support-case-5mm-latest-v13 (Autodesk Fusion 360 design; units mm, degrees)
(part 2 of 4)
sketch "Sketch28" plane through (0, 0, 19.25) normal (0, 0, 1) x axis (-1, 0, 0)
  line L1 (-86.4, -52.5) -> (-80.4, -52.5)
  line L2 (-86.4, -3.4983) -> (-86.4, -52.5)
  line L3 (-80.4, -3.4983) -> (-86.4, -3.4983)
  line L4 (-80.4, -52.5) -> (-80.4, -3.4983)
  line L5 (-22.4, -3.5) -> (-28.4, -3.5)
  line L6 (-22.4, -52.5) -> (-22.4, -3.5)
  line L7 (-28.4, -52.5) -> (-22.4, -52.5)
  line L8 (-28.4, -3.5) -> (-28.4, -52.5)
  line L9 (-25.4, -49.5) -> (-83.4, -49.5)
  line L10 (-25.4, -55.5) -> (-25.4, -49.5)
  line L11 (-83.4, -55.5) -> (-25.4, -55.5)
  line L12 (-83.4, -49.5) -> (-83.4, -55.5)
  line L13 (-74.4, -49.5) -> (-80.4, -49.5)
  line L14 (-80.4, -43.5) -> (-80.4, -49.5)
  line L15 (-74.4, -49.5) -> (-80.4, -43.5)
  line L16 (-34.4, -49.5) -> (-28.4, -49.5)
  line L17 (-28.4, -43.5) -> (-28.4, -49.5)
  line L18 (-28.4, -43.5) -> (-34.4, -49.5)
  circle C1 centre (-83.4, -3.5) radius 3
  circle C2 centre (-83.4, -52.5) radius 3
  circle C3 centre (-25.4, -52.5) radius 3
  point P5 (-86.4, -3.4983)
  point P13 (-25.4, -55.5)
  point P11 (-83.4, -49.5)
  point P17 (-80.4, -49.5)
  point P20 (-28.4, -49.5)
  point P18 (-74.4, -49.5)
  point P19 (-80.4, -43.5)
  point P21 (-34.4, -49.5)
  point P22 (-28.4, -43.5)
  horizontal L1
  vertical L2
  horizontal L3
  vertical L4
  coincident C1 P5
  horizontal L5
  vertical L6
  horizontal L7
  vertical L8
  horizontal L9
  vertical L10
  horizontal L11
  vertical L12
  coincident P13 C3
  coincident P11 C2
  coincident L9 P17
  coincident L4 P17
  perpendicular L4 L13
  perpendicular L9 L14
  coincident L8 P20
  coincident L9 P20
  perpendicular L8 L16
  perpendicular L9 L17
  dimension "d218" distance P17 P18 = 6
  dimension "d219" distance P17 P19 = 6
  dimension "d220" distance P20 P21 = 6
  dimension "d221" distance P20 P22 = 6
extrude "Extrude30" add sketch "Sketch28" along normal blind 1
extrude "Extrude31" add of existing geometry blind 2
fillet "Fillet25" radius 10.5
move "Move3"
extrude "Extrude32" add of existing geometry blind 1.85
offset_faces "OffsetFaces6" distance -0.2
offset_faces "OffsetFaces7" distance -0.2
combine "Combine2"
work_plane "WorkPlane3" AlongDistance 1
sketch "Sketch29" plane through (88.7, 27.8941, 21.675) normal (1, 0, 0) x axis (0, 1, 0)
  line L1 (25, 0) -> (-25, 0)
  line L2 (13, -1.5) -> (13, 0)
  line L3 (-13, 0) -> (0, 0)
  line L4 (-13, -2) -> (-13, 0)
  line L5 (13, 0) -> (-13, 0)
  line L6 (13, -1.5) -> (13, 0)
  line L7 (-13, -1.5) -> (13, -1.5)
  line L8 (-13, 0) -> (-13, -1.5)
  point P1 (0, 0)
  point P6 (0, 0)
  point P4 (13, 0)
  point P7 (-13, 0)
  horizontal L1
  vertical L2
  horizontal L3
  vertical L4
  coincident P1 P6
  horizontal L5
  vertical L6
  horizontal L7
  vertical L8
  dimension "d233" distance P1 P4 = 13
  dimension "d235" distance P6 P7 = 13
  dimension "d237" distance L3 L7 = 1.5
revolve "Revolve3" sketch "Sketch29" AlongAngle 360
fillet "Fillet26" radius 1
sketch "Sketch30" plane through (0, 0, 23.1) normal (0, 0, 1) x axis (-1, 0, 0)
  line L1 (-4.6, -56.802) -> (-84.2, -56.802)
  line L2 (-1.1, -2.6862) -> (-1.1, -53.302)
  line L3 (-84.4, 0.8138) -> (-4.6, 0.8138)
  line L4 (-87.7, -53.302) -> (-87.7, -2.4862)
  line L5 (-86.7, -53.302) -> (-86.7, -2.4862)
  line L6 (-4.6, -55.802) -> (-84.2, -55.802)
  line L7 (-2.1, -2.6862) -> (-2.1, -53.302)
  line L8 (-84.4, -0.1862) -> (-4.6, -0.1862)
  arc A1 centre (-84.2, -53.302) radius 3.5 clockwise from (-84.2, -56.802) to (-87.7, -53.302)
  arc A2 centre (-4.6, -53.302) radius 3.5 clockwise from (-1.1, -53.302) to (-4.6, -56.802)
  arc A3 centre (-4.6, -2.6862) radius 3.5 clockwise from (-4.6, 0.8138) to (-1.1, -2.6862)
  arc A4 centre (-84.4, -2.4862) radius 3.3 clockwise from (-87.7, -2.4862) to (-84.4, 0.8138)
  arc A5 centre (-84.2, -53.302) radius 2.5 clockwise from (-84.2, -55.802) to (-86.7, -53.302)
  arc A6 centre (-4.6, -53.302) radius 2.5 clockwise from (-2.1, -53.302) to (-4.6, -55.802)
  arc A7 centre (-4.6, -2.6862) radius 2.5 clockwise from (-4.6, -0.1862) to (-2.1, -2.6862)
  arc A8 centre (-84.4, -2.4862) radius 2.3 clockwise from (-86.7, -2.4862) to (-84.4, -0.1862)
  circle C1 centre (-44.4, -27.9441) radius 5
  circle C2 centre (-44.4, -27.9441) radius 7
  circle C3 centre (-44.4, -27.9441) radius 10
  circle C4 centre (-44.4, -27.9441) radius 12
  circle C5 centre (-44.4, -27.9441) radius 15
  circle C6 centre (-44.4, -27.9441) radius 17
  circle C7 centre (-44.4, -27.9441) radius 20
  circle C8 centre (-44.4, -27.9441) radius 22
  circle C9 centre (-44.4, -27.9441) radius 25
  circle C10 centre (-44.4, -27.9441) radius 27
  circle C11 centre (-44.4, -27.9441) radius 30
  circle C12 centre (-44.4, -27.9441) radius 32
  circle C13 centre (-44.4, -27.9441) radius 35
  circle C14 centre (-44.4, -27.9441) radius 37.5
  circle C15 centre (-44.4, -27.9441) radius 40
  circle C16 centre (-44.4, -27.9441) radius 42
  circle C17 centre (-44.4, -27.9441) radius 45
  circle C18 centre (-44.4, -27.9441) radius 47
  concentric C1 C3
  concentric C1 C4
  concentric C4 C5
  concentric C1 C6
  concentric C4 C7
  concentric C5 C8
  concentric C7 C9
  concentric C4 C10
  concentric C4 C11
  concentric C8 C12
  concentric C7 C13
  concentric C7 C14
  concentric C11 C15
  concentric C14 C16
  concentric C9 C17
  concentric C16 C18
  dimension "d241" = -1
  dimension "d242" diameter C1 = 10
  dimension "d243" = 2
  dimension "d244" diameter C3 = 20
  dimension "d245" diameter C4 = 24
  dimension "d246" diameter C5 = 30
  dimension "d247" diameter C6 = 34
  dimension "d248" diameter C7 = 40
  dimension "d249" diameter C8 = 44
  dimension "d250" diameter C9 = 50
  dimension "d251" diameter C10 = 54
  dimension "d252" diameter C11 = 60
  dimension "d253" diameter C12 = 64
  dimension "d254" diameter C13 = 70
  dimension "d255" diameter C14 = 75
  dimension "d256" diameter C15 = 80
  dimension "d257" diameter C16 = 84
  dimension "d258" diameter C17 = 90
  dimension "d259" diameter C18 = 94
extrude "Extrude33" cut sketch "Sketch30" profile of A8 L5 A5 L6 A6 L8 L7 A7 C1 C2 C3 C4 C5 C6 C7 C8 C9 C10 C11 C12 C13 C14 C15 C16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 against normal blind 2.85
sketch "Sketch31" plane through (0, 0, 23.1) normal (0, 0, 1) x axis (-1, 0, 0)
  line L1 (-28.6539, -55.802) -> (-23.2118, -55.802)
  line L2 (-23.081, -0.1862) -> (-28.4783, -0.1862)
  line L3 (-75.9198, -0.1862) -> (-79.8189, -0.1862)
  line L4 (-79.7403, -55.802) -> (-75.8315, -55.802)
  line L5 (-86.7, -12.5913) -> (-86.7, -43.297)
  line L6 (-69.6141, -0.1862) -> (-73.2011, -0.1862)
  line L7 (-73.1043, -55.802) -> (-69.5036, -55.802)
  line L8 (-12.9685, -55.802) -> (-9.0597, -55.802)
  line L9 (-8.9811, -0.1862) -> (-12.8802, -0.1862)
  line L10 (-2.1, -43.297) -> (-2.1, -12.5913)
  line L11 (-6.5458, -55.802) -> (-4.6, -55.802)
  line L12 (-2.1, -53.302) -> (-2.1, -48.4309)
  line L13 (-19.2964, -55.802) -> (-15.6957, -55.802)
  line L14 (-15.5989, -0.1862) -> (-19.1859, -0.1862)
  line L15 (-33.0202, -0.1862) -> (-55.7798, -0.1862)
  line L16 (-55.5328, -55.802) -> (-33.2672, -55.802)
  line L17 (-82.3276, -0.1862) -> (-84.4, -0.1862)
  line L18 (-86.7, -2.4862) -> (-86.7, -7.4573)
  line L19 (-60.3217, -0.1862) -> (-65.719, -0.1862)
  line L20 (-65.5882, -55.802) -> (-60.1461, -55.802)
  line L21 (-2.1, -7.4573) -> (-2.1, -2.6862)
  line L22 (-4.6, -0.1862) -> (-6.4724, -0.1862)
  line L23 (-86.7, -48.4309) -> (-86.7, -53.302)
  line L24 (-84.2, -55.802) -> (-82.2542, -55.802)
  line L25 (-4.6, -56.802) -> (-84.2, -56.802)
  line L26 (-1.1, -2.6862) -> (-1.1, -53.302)
  line L27 (-84.4, 0.8138) -> (-4.6, 0.8138)
  line L28 (-87.7, -53.302) -> (-87.7, -2.4862)
  line L29 (-86.7, -2.4862) -> (-84.4, -0.1862)
  line L30 (-86.0263, -0.8599) -> (-85.55, -1.3362)
  curve K1 (-44.4, -27.9441) -> (-2.8322, -0.9185)
  curve K2 (-2.2872, -1.7569) -> (-86.5717, -1.6981)
  curve K3 (-3.3773, -0.0801) -> (-85.481, -0.0217)
  line L31 (9.9934, -28.0452) -> (-44.4, -27.9441)
  curve K4 (-3.4811, -55.9604) -> (-85.5844, -55.7137)
  curve K5 (-2.3847, -54.2877) -> (-86.6689, -54.0333)
  line L32 (-86.8, -54.8) -> (-86.6689, -54.0333)
  line L33 (-85.5844, -55.7137) -> (-86.8, -54.8)
  line L34 (-2.2132, -54.4166) -> (-2.3847, -54.2877)
  line L35 (-3.4811, -55.9604) -> (-2.2132, -54.4166)
  line L36 (-2.087, -1.05) -> (-3.3773, -0.0801)
  line L37 (-2.2872, -1.7569) -> (-2.087, -1.05)
  line L38 (-86.5717, -0.8599) -> (-86.5717, -1.6981)
  line L39 (-85.481, -0.0217) -> (-86.5717, -0.8599)
  arc A1 centre (-44.4, -27.9441) radius 35 clockwise from (-23.081, -0.1862) to (-23.2118, -55.802)
  arc A2 centre (-44.4, -27.9441) radius 32 clockwise from (-28.4783, -0.1862) to (-28.6539, -55.802)
  arc A3 centre (-44.4, -27.9441) radius 45 clockwise from (-86.7, -12.5913) to (-79.8189, -0.1862)
  arc A4 centre (-44.4, -27.9441) radius 42 clockwise from (-75.8315, -55.802) to (-75.9198, -0.1862)
  arc A5 centre (-44.4, -27.9441) radius 45 clockwise from (-79.7403, -55.802) to (-86.7, -43.297)
  arc A6 centre (-44.4, -27.9441) radius 40 clockwise from (-73.1043, -55.802) to (-73.2011, -0.1862)
  arc A7 centre (-44.4, -27.9441) radius 37.5 clockwise from (-69.5036, -55.802) to (-69.6141, -0.1862)
  arc A8 centre (-44.4, -27.9441) radius 45 clockwise from (-2.1, -43.297) to (-9.0597, -55.802)
  arc A9 centre (-44.4, -27.9441) radius 42 clockwise from (-12.8802, -0.1862) to (-12.9685, -55.802)
  arc A10 centre (-44.4, -27.9441) radius 45 clockwise from (-8.9811, -0.1862) to (-2.1, -12.5913)
  arc A11 centre (-4.6, -53.302) radius 2.5 clockwise from (-2.1, -53.302) to (-4.6, -55.802)
  arc A12 centre (-44.4, -27.9441) radius 47 clockwise from (-2.1, -48.4309) to (-6.5458, -55.802)
  arc A13 centre (-44.4, -27.9441) radius 40 clockwise from (-15.5989, -0.1862) to (-15.6957, -55.802)
  arc A14 centre (-44.4, -27.9441) radius 37.5 clockwise from (-19.1859, -0.1862) to (-19.2964, -55.802)
  arc A15 centre (-44.4, -27.9441) radius 30 clockwise from (-33.0202, -0.1862) to (-33.2672, -55.802)
  arc A16 centre (-44.4, -27.9441) radius 30 clockwise from (-55.5328, -55.802) to (-55.7798, -0.1862)
  arc A17 centre (-84.4, -2.4862) radius 2.3 clockwise from (-86.7, -2.4862) to (-84.4, -0.1862)
  arc A18 centre (-44.4, -27.9441) radius 47 clockwise from (-86.7, -7.4573) to (-82.3276, -0.1862)
  arc A19 centre (-44.4, -27.9441) radius 35 clockwise from (-65.5882, -55.802) to (-65.719, -0.1862)
  arc A20 centre (-44.4, -27.9441) radius 32 clockwise from (-60.1461, -55.802) to (-60.3217, -0.1862)
  arc A21 centre (-4.6, -2.6862) radius 2.5 clockwise from (-4.6, -0.1862) to (-2.1, -2.6862)
  arc A22 centre (-44.4, -27.9441) radius 47 clockwise from (-6.4724, -0.1862) to (-2.1, -7.4573)
  arc A23 centre (-84.2, -53.302) radius 2.5 clockwise from (-84.2, -55.802) to (-86.7, -53.302)
  arc A24 centre (-44.4, -27.9441) radius 47 clockwise from (-82.2542, -55.802) to (-86.7, -48.4309)
  arc A25 centre (-84.2, -53.302) radius 3.5 clockwise from (-84.2, -56.802) to (-87.7, -53.302)
  arc A26 centre (-4.6, -53.302) radius 3.5 clockwise from (-1.1, -53.302) to (-4.6, -56.802)
  arc A27 centre (-4.6, -2.6862) radius 3.5 clockwise from (-4.6, 0.8138) to (-1.1, -2.6862)
  arc A28 centre (-84.4, -2.4862) radius 3.3 clockwise from (-87.7, -2.4862) to (-84.4, 0.8138)
  point P36 (-84.4, -0.1862)
  point P63 (-84.4, -0.1862)
  point P37 (-86.7, -2.4862)
  point P64 (-86.7, -2.4862)
  point P65 (-85.55, -1.3362)
  point P66 (-86.0263, -0.8599)
  point P67 (-2.8322, -0.9185)
  point P69 (-86.5717, -1.6981)
  point P76 (-86.6689, -54.0333)
  point P70 (-2.2872, -1.7569)
  point P77 (-2.3847, -54.2877)
  point P71 (-85.481, -0.0217)
  point P74 (-85.5844, -55.7137)
  point P72 (-3.3773, -0.0801)
  point P75 (-3.4811, -55.9604)
  coincident P36 P63
  coincident P37 P64
  midpoint L29 P65
  midpoint A17 P66
  midpoint A21 P67
  symmetric P69 L31 P76
  symmetric P70 L31 P77
  symmetric K2 L31 K5
  symmetric P71 L31 P74
  symmetric P72 L31 P75
  symmetric K3 L31 K4
  parallel L33 L34
  parallel L34 L36
  vertical L38
  dimension "d264" = 1
  dimension "d265" = -1
extrude "Extrude34" add sketch "Sketch31" profile of A1 A2 A3 A4 A5 A6 A7 A8 A9 A10 A11 A12 A13 A14 A15 A16 A17 A18 A19 A20 A21 A22 A23 A24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 against normal blind 2.85
extrude "Extrude35" cut of existing geometry blind -0.519
delete_face "DeleteFace9"
delete_face "DeleteFace10"
delete_face "DeleteFace11"
delete_face "DeleteFace12"
extrude "Extrude36" add of existing geometry blind 0.719 (= "2 mm - 1.281 mm")
fillet "Fillet27" radius 1.5
delete_face "DeleteFace13"
move_face "MoveFace1" TranslateX 0.1 TranslateY 0 TranslateZ 0
move_face "MoveFace2" TranslateX 1.3 TranslateY 0 TranslateZ 0
move_face "MoveFace3" TranslateX 0.15 TranslateY 0 TranslateZ 0
move_face "MoveFace4" TranslateX 0.15 TranslateY 0 TranslateZ 0
move_face "MoveFace5" TranslateX 0.05 TranslateY 0 TranslateZ 0
delete_face "DeleteFace14"
delete_face "DeleteFace15"
delete_face "DeleteFace16"
delete_face "DeleteFace17"
delete_face "DeleteFace18"
delete_face "DeleteFace19"
delete_face "DeleteFace20"
delete_face "DeleteFace21"
delete_face "DeleteFace22"
delete_face "DeleteFace23"
delete_face "DeleteFace24"
delete_face "DeleteFace25"
delete_face "DeleteFace26"
delete_face "DeleteFace27"
delete_face "DeleteFace28"
delete_face "DeleteFace29"
delete_face "DeleteFace30"
delete_face "DeleteFace31"
delete_face "DeleteFace32"
delete_face "DeleteFace33"
delete_face "DeleteFace34"
delete_face "DeleteFace35"
delete_face "DeleteFace36"
delete_face "DeleteFace37"
delete_face "DeleteFace38"
delete_face "DeleteFace39"
delete_face "DeleteFace40"
sketch "Sketch32" plane through (0, 58.002, 0) normal (0, 1, 0) x axis (-1, 0, 0)
  line L1 (-71.2, 6.8) -> (-80.2, 6.8)
  line L2 (-70.7, 3) -> (-70.7, 6.3)
  line L3 (-80.2, 2.5) -> (-71.2, 2.5)
  line L4 (-80.7, 6.3) -> (-80.7, 3)
  line L5 (-51.05, 2.5) -> (-43.95, 2.5)
  line L6 (-51.55, 6) -> (-51.55, 3)
  line L7 (-43.95, 6.5) -> (-51.05, 6.5)
  line L8 (-43.45, 3) -> (-43.45, 6)
  line L9 (-64.45, 2.5) -> (-57.35, 2.5)
  line L10 (-64.95, 6) -> (-64.95, 3)
  line L11 (-57.35, 6.5) -> (-64.45, 6.5)
  line L12 (-56.85, 3) -> (-56.85, 6)
  line L13 (-82.05, 1) -> (-82.05, 11.0521)
  line L14 (-28.2507, 1) -> (-82.05, 1)
  line L15 (-28.2507, 11.0521) -> (-28.2507, 1)
  line L16 (-82.05, 11.0521) -> (-28.2507, 11.0521)
  line L17 (-40.45, -0.5) -> (-40.45, 12.5584)
  line L18 (-26.7633, 12.5584) -> (-40.45, 12.5584)
  line L19 (-26.7633, -0.6691) -> (-26.7633, 12.5584)
  line L20 (-40.45, -0.6691) -> (-26.7633, -0.6691)
  line L21 (-40.45, 12.5584) -> (-40.45, -0.6691)
  arc A1 centre (-71.2, 6.3) radius 0.5 clockwise from (-71.2, 6.8) to (-70.7, 6.3)
  arc A2 centre (-71.2, 3) radius 0.5 clockwise from (-70.7, 3) to (-71.2, 2.5)
  arc A3 centre (-80.2, 3) radius 0.5 clockwise from (-80.2, 2.5) to (-80.7, 3)
  arc A4 centre (-80.2, 6.3) radius 0.5 clockwise from (-80.7, 6.3) to (-80.2, 6.8)
  arc A5 centre (-43.95, 3) radius 0.5 clockwise from (-43.45, 3) to (-43.95, 2.5)
  arc A6 centre (-51.05, 3) radius 0.5 clockwise from (-51.05, 2.5) to (-51.55, 3)
  arc A7 centre (-51.05, 6) radius 0.5 clockwise from (-51.55, 6) to (-51.05, 6.5)
  arc A8 centre (-43.95, 6) radius 0.5 clockwise from (-43.95, 6.5) to (-43.45, 6)
  arc A9 centre (-57.35, 3) radius 0.5 clockwise from (-56.85, 3) to (-57.35, 2.5)
  arc A10 centre (-64.45, 3) radius 0.5 clockwise from (-64.45, 2.5) to (-64.95, 3)
  arc A11 centre (-64.45, 6) radius 0.5 clockwise from (-64.95, 6) to (-64.45, 6.5)
  arc A12 centre (-57.35, 6) radius 0.5 clockwise from (-57.35, 6.5) to (-56.85, 6)
  perpendicular L14 L17
  horizontal L18
  vertical L19
  horizontal L20
  vertical L21
  dimension "d289" distance L8 L17 = 3
extrude "Extrude37" add sketch "Sketch32" profile of L14 L15 L16 L17 L18 L19 L20 L21 along normal blind 1.8
delete_face "DeleteFace41"
fillet "Fillet29" radius 1.5
delete_face "DeleteFace43"
sketch "Sketch33" plane through (0, 59.802, 0) normal (0, 1, 0) x axis (-1, 0, 0)
  line L1 (-40.45, -0.4697) -> (-40.45, 12.5218)
  line L2 (-83.5197, -0.4697) -> (-40.45, -0.4697)
  line L3 (-83.5197, 12.5218) -> (-83.5197, -0.4697)
  line L4 (-40.45, 12.5218) -> (-83.5197, 12.5218)
  line L5 (-4.6, -2.019) -> (-84.2, -2.019)
  line L6 (-4.6, 21.6) -> (-4.6, -2.019)
  line L7 (-84.2, 21.6) -> (-4.6, 21.6)
  line L8 (-84.2, -2.019) -> (-84.2, 21.6)
  line L9 (-83.5197, 12.5218) -> (-40.45, 12.5218)
  line L10 (-83.5197, -0.4697) -> (-83.5197, 12.5218)
  line L11 (-40.45, -0.4697) -> (-83.5197, -0.4697)
  line L12 (-40.45, 12.5218) -> (-40.45, -0.4697)
  line L13 (-83.5197, 9.7703) -> (-83.5197, -0.4697)
  line L14 (-40.45, 9.7703) -> (-83.5197, 9.7703)
  point P2 (-40.45, 12.5218)
  point P14 (-40.45, 12.5218)
  point P19 (-40.45, 9.7703)
  point P16 (-83.5197, -0.4697)
  point P18 (-83.5197, 9.7703)
  horizontal L9
  vertical L10
  horizontal L11
  vertical L12
  coincident P2 P14
  perpendicular L11 L13
  coincident L1 P19
  perpendicular L1 L14
  dimension "d330" distance P16 P18 = 10.24 (= "( 5.12 * 2 ) * 1 mm")
extrude "Extrude38" cut sketch "Sketch33" profile of L1 L2 L3 L4 L9 L10 L11 L12 L13 L14 against normal blind 1.8
delete_face "DeleteFace44"
delete_face "DeleteFace46"
delete_face "DeleteFace49"
extrude "Extrude48" add sketch "Sketch33" profile of L1 L3 L4 L9 L10 L12 L14 against normal blind 2.8
extrude "Extrude39" cut of existing geometry blind -0.18 (= "-( 3 mm - 2.82 mm )")
fillet "Fillet30" radius 1.5
delete_face "DeleteFace51"
delete_face "DeleteFace52"
delete_face "DeleteFace53"
delete_face "DeleteFace54"
delete_face "DeleteFace55"
delete_face "DeleteFace56"
delete_face "DeleteFace57"
delete_face "DeleteFace58"
delete_face "DeleteFace59"
delete_face "DeleteFace60"
delete_face "DeleteFace61"
delete_face "DeleteFace62"
delete_face "DeleteFace63"
offset_faces "OffsetFaces8" distance 1
delete_face "DeleteFace64"
extrude "Extrude40" new body of existing geometry blind -2.9
delete_face "DeleteFace65"
combine "Combine3"
combine "Combine4"
extrude "Extrude41" add of existing geometry blind -2.919
extrude "Extrude42" new body of existing geometry blind -2.919
delete_face "DeleteFace66"
extrude "Extrude43" add of existing geometry blind -2.919
fillet "Fillet32" radius 2.25
sketch "Sketch34" plane through (0, 0, -1.519) normal (0, 0, 1) x axis (-1, 0, 0)
  curve K1 (-20.1586, -3.5211) -> (-28.054, 1.0138)
  line L1 (-80.7188, 1.0138) -> (-28.054, 1.0138)
  curve K2 (-80.7188, 1.0138) -> (-78.15, -3.5)
  curve K3 (-78.15, -3.5) -> (-87.9, -6.2042)
  line L2 (-87.9, -19.9875) -> (-87.9, -6.2042)
  line L3 (-84.9, -19.9875) -> (-87.9, -19.9875)
  line L4 (-83.9, -33.6) -> (-83.9, -20.9875)
  line L5 (-87.9, -34.6) -> (-84.9, -34.6)
  line L6 (-87.9, -49.7958) -> (-87.9, -34.6)
  curve K4 (-87.9, -49.7958) -> (-78.15, -52.5)
  curve K5 (-78.15, -52.5) -> (-80.6992, -57.002)
  line L7 (-28.1228, -57.002) -> (-80.6992, -57.002)
  curve K6 (-28.1228, -57.002) -> (-20.1538, -52.5109)
  curve K7 (-20.1538, -52.5109) -> (-22.6848, -57.002)
  line L8 (-4.4, -57.002) -> (-22.6848, -57.002)
  line L9 (-0.9, -2.4862) -> (-0.9, -53.502)
  line L10 (-22.7633, 1.0138) -> (-4.4, 1.0138)
  curve K8 (-22.7633, 1.0138) -> (-20.1586, -3.5211)
  line L11 (-87.7975, -50) -> (-1.0165, -50)
  line L12 (-87.7975, -5) -> (-87.7975, -50)
  line L13 (-1.0165, -5) -> (-87.7975, -5)
  line L14 (-1.0165, -50) -> (-1.0165, -5)
  curve K9
  curve K10
  curve K11
  curve K12
  curve K13
  curve K14
  curve K15
  curve K16
  curve K17
  curve K18
  curve K19
  curve K20
  arc A1 centre (-84.9, -20.9875) radius 1 clockwise from (-84.9, -19.9875) to (-83.9, -20.9875)
  arc A2 centre (-84.9, -33.6) radius 1 clockwise from (-83.9, -33.6) to (-84.9, -34.6)
  arc A3 centre (-4.4, -53.502) radius 3.5 clockwise from (-0.9, -53.502) to (-4.4, -57.002)
  arc A4 centre (-4.4, -2.4862) radius 3.5 clockwise from (-4.4, 1.0138) to (-0.9, -2.4862)
  point P33 (-87.7975, -5)
  point P31 (-1.0165, -50)
  horizontal L11
  vertical L12
  horizontal L13
  vertical L14
  coincident P33
  coincident P31
  coincident P33
  coincident P31
  coincident P33
  dimension "d315" Text1-Height = 4.5
  dimension "d318" Text2-Height = 3.5
  dimension "d471" Text3-Height = 4
extrude "Extrude44" cut sketch "Sketch34" against normal blind 0.2
sketch "Sketch35" plane through (90.7, 0, 0) normal (1, 0, 0) x axis (0, 1, 0)
  line L1 (53.302, -2.019) -> (35.6, -2.019)
  line L2 (53.302, 21.6) -> (53.302, -2.019)
  line L3 (2.6862, 21.6) -> (53.302, 21.6)
  line L4 (2.6862, -2.019) -> (2.6862, 21.6)
  line L5 (18.9875, -2.019) -> (2.6862, -2.019)
  line L6 (18.9875, 0.4) -> (18.9875, -2.019)
  line L7 (33.6, 2.4) -> (20.9875, 2.4)
  line L8 (35.6, -2.019) -> (35.6, 0.4)
  line L9 (53.302, 1.4134) -> (2.6862, 1.4134)
  line L10 (55.9941, 1.4134) -> (27.9941, 1.4134)
  line L11 (37.5941, 1.4134) -> (55.9941, 1.4134)
  line L12 (37.5941, 5.5134) -> (37.5941, 1.4134)
  line L13 (42.6941, 1.4134) -> (55.9941, 1.4134)
  line L14 (42.6941, 5.5134) -> (37.5941, 5.5134)
  line L15 (42.6941, 1.4134) -> (37.5941, 1.4134)
  line L16 (43.8675, 1.7824) -> (43.1406, 5.4642)
  arc A1 centre (20.9875, 0.4) radius 2 clockwise from (18.9875, 0.4) to (20.9875, 2.4)
  arc A2 centre (33.6, 0.4) radius 2 clockwise from (33.6, 2.4) to (35.6, 0.4)
  circle C1 centre (37.5941, 3.4634) radius 2.05
  circle C2 centre (42.6941, 3.4634) radius 2.05
  circle C3 centre (39.6441, 3.4634) radius 2.05
  point P19 (27.9941, 1.4134)
  point P23 (37.5941, 3.4634)
  point P21 (37.5941, 1.4134)
  point P24 (42.6941, 1.4134)
  point P26 (42.6941, 5.5134)
  point P27 (39.6441, 3.4634)
  point P28 (43.1406, 5.4642)
  point P29 (43.8675, 1.7824)
  point P20 (55.9941, 1.4134)
  point P22 (37.5941, 5.5134)
  midpoint L9 P19
  parallel L9 L11
  perpendicular L10 L12
  midpoint L12 P23
  coincident P21 C1
  parallel L11 L13
  coincident P24 C2
  coincident C2 P26
  tangent C2 L14
  perpendicular L12 L14
  tangent C2 L15
  coincident C1 P27
  tangent L15 C3
  coincident C2 P28
  coincident C2 P29
  dimension "d320" distance P19 P20 = 28 (= "( 56 / 2 ) * 1 mm")
  dimension "d321" distance P20 P21 = 18.4
  dimension "d322" distance P21 P22 = 4.1
  dimension "d323" distance P20 P24 = 13.3
extrude "Extrude45" cut sketch "Sketch35" profile of L9 L10 L11 L12 C1 C2 L14 L15 against normal blind 2.8
sketch "Sketch36" plane through (90.7, 0, 0) normal (1, 0, 0) x axis (0, 1, 0)
  line L1 (37.5941, 1.4134) -> (42.6941, 1.4134)
  line L2 (42.6941, 5.5134) -> (37.5941, 5.5134)
  line L3 (33.6, 2.4) -> (20.9875, 2.4)
  line L4 (35.6, -2.019) -> (35.6, 0.4)
  line L5 (53.302, -2.019) -> (35.6, -2.019)
  line L6 (53.302, 21.6) -> (53.302, -2.019)
  line L7 (2.6862, 21.6) -> (53.302, 21.6)
  line L8 (2.6862, -2.019) -> (2.6862, 21.6)
  line L9 (18.9875, -2.019) -> (2.6862, -2.019)
  line L10 (18.9875, 0.4) -> (18.9875, -2.019)
  line L11 (42.0276, 9.5417) -> (40.8255, 7.1376)
  line L12 (38.6336, 8.2336) -> (39.8356, 10.6377)
  line L13 (40.9316, 10.0897) -> (39.7296, 7.6856)
  line L14 (32.6474, 3.0718) -> (31.5271, 3.9384)
  line L15 (32.7999, 5.5837) -> (33.9202, 4.7171)
  line L16 (33.2838, 3.8945) -> (32.1635, 4.7611)
  line L17 (39.809, -1.2436) -> (38.3992, -0.0011)
  line L18 (39.1812, 0.8862) -> (40.591, -0.3564)
  line L19 (40.2, -0.8) -> (38.7902, 0.4426)
  line L20 (36.6258, -0.6871) -> (36.1258, 0.3129)
  line L21 (36.8742, 0.6871) -> (37.3742, -0.3129)
  line L22 (37, -0.5) -> (36.5, 0.5)
  line L23 (44.3847, -0.2206) -> (43.6433, -1.2821)
  line L24 (42.503, -0.4857) -> (43.2444, 0.5758)
  line L25 (44.2127, 0.7478) -> (42.6749, -1.4541)
  line L26 (47.0891, -0.5864) -> (45.9587, 2.459)
  line L27 (47.497, 3.03) -> (48.6275, -0.0154)
  line L28 (48.1438, -1.07) -> (46.4424, 3.5137)
  arc A1 centre (37.5941, 3.4634) radius 2.05 clockwise from (37.5941, 1.4134) to (37.5941, 5.5134)
  arc A2 centre (42.6941, 3.4634) radius 2.05 clockwise from (42.6941, 5.5134) to (42.6941, 1.4134)
  arc A3 centre (33.6, 0.4) radius 2 clockwise from (33.6, 2.4) to (35.6, 0.4)
  arc A4 centre (20.9875, 0.4) radius 2 clockwise from (18.9875, 0.4) to (20.9875, 2.4)
  arc A5 centre (40.9316, 10.0897) radius 1.2254 clockwise from (39.8356, 10.6377) to (42.0276, 9.5417)
  arc A6 centre (39.7296, 7.6856) radius 1.2254 clockwise from (40.8255, 7.1376) to (38.6336, 8.2336)
  arc A7 centre (33.2838, 3.8945) radius 1.0401 clockwise from (33.9202, 4.7171) to (32.6474, 3.0718)
  arc A8 centre (32.1635, 4.7611) radius 1.0401 clockwise from (31.5271, 3.9384) to (32.7999, 5.5837)
  arc A9 centre (40.2, -0.8) radius 0.5914 clockwise from (40.591, -0.3564) to (39.809, -1.2436)
  arc A10 centre (38.7902, 0.4426) radius 0.5914 clockwise from (38.3992, -0.0011) to (39.1812, 0.8862)
  arc A11 centre (37, -0.5) radius 0.4184 clockwise from (37.3742, -0.3129) to (36.6258, -0.6871)
  arc A12 centre (36.5, 0.5) radius 0.4184 clockwise from (36.1258, 0.3129) to (36.8742, 0.6871)
  arc A13 centre (43.8145, 0.1776) radius 0.6955 clockwise from (43.2444, 0.5758) to (44.3847, -0.2206)
  arc A14 centre (43.0731, -0.8839) radius 0.6955 clockwise from (43.6433, -1.2821) to (42.503, -0.4857)
  arc A15 centre (47.8583, -0.3009) radius 0.8205 clockwise from (48.6275, -0.0154) to (47.0891, -0.5864)
  arc A16 centre (46.7279, 2.7445) radius 0.8205 clockwise from (45.9587, 2.459) to (47.497, 3.03)
  point P53 (42.6749, -1.4541)
  point P54 (44.2127, 0.7478)
  point P61 (46.4424, 3.5137)
  point P62 (48.1438, -1.07)
  tangent L11 A5
  tangent A5 L12
  parallel L11 L12
  tangent L12 A6
  tangent L11 A6
  tangent L14 A7
  tangent A7 L15
  parallel L14 L15
  tangent L15 A8
  tangent L14 A8
  tangent L17 A9
  tangent A9 L18
  parallel L17 L18
  tangent L18 A10
  tangent L17 A10
  tangent L20 A11
  tangent A11 L21
  parallel L20 L21
  tangent L21 A12
  tangent L20 A12
  tangent L23 A13
  tangent A13 L24
  parallel L23 L24
  tangent L24 A14
  tangent L23 A14
  midpoint A14 P53
  midpoint A13 P54
  tangent L26 A15
  tangent A15 L27
  parallel L26 L27
  tangent L27 A16
  tangent L26 A16
  midpoint A16 P61
  midpoint A15 P62
extrude "Extrude46" cut sketch "Sketch36" profile of L11 A5 L12 A6 L14 A7 L15 A8 L17 A9 L18 A10 L20 A11 L21 A12 L23 A13 L24 A14 L26 A15 L27 A16 against normal blind 2.8
sketch "Sketch37" plane through (0, 59.802, 0) normal (0, 1, 0) x axis (-1, 0, 0)
  line L1 (-84.2, -2.019) -> (-84.2, 21.6)
  line L2 (-4.6, -2.019) -> (-84.2, -2.019)
  line L3 (-4.6, 21.6) -> (-4.6, -2.019)
  line L4 (-84.2, 21.6) -> (-4.6, 21.6)
  line L5 (-39.5871, -1.2425) -> (-24.6167, -1.2425)
  line L6 (-39.5871, 12.8777) -> (-39.5871, -1.2425)
  line L7 (-34.1048, 11.2793) -> (-36.2337, 8.6349)
  line L8 (-38.0242, 10.0763) -> (-35.8952, 12.7207)
  line L9 (-35, 12) -> (-37.1289, 9.3556)
  line L10 (-35.4481, 3.134) -> (-37.4481, 0.134)
  line L11 (-39.0681, 1.214) -> (-37.0681, 4.214)
  line L12 (-36.2581, 3.674) -> (-38.2581, 0.674)
  line L13 (-29.1506, 11.3422) -> (-32.0744, 7.687)
  line L14 (-34.1698, 9.3632) -> (-31.2459, 13.0183)
  line L15 (-30.1982, 12.1802) -> (-33.1221, 8.5251)
  line L16 (-29.7365, 6.1071) -> (-30.3476, 4.7139)
  line L17 (-31.6524, 5.2861) -> (-31.0413, 6.6794)
  line L18 (-30.3889, 6.3932) -> (-31, 5)
  line L19 (-35.2431, 7.2215) -> (-32.6686, 4.5243)
  line L20 (-33.4899, 3.7403) -> (-36.0645, 6.4375)
  line L21 (-35.6538, 6.8295) -> (-33.0792, 4.1323)
  line L22 (-29.7705, 1.5082) -> (-31.8892, -0.787)
  line L23 (-33.2118, 0.4339) -> (-31.0932, 2.7291)
  line L24 (-30.4319, 2.1186) -> (-32.5505, -0.1766)
  line L25 (-26.7609, 10.6458) -> (-25.751, 8.6279)
  line L26 (-26.9306, 8.0376) -> (-27.9405, 10.0554)
  line L27 (-27.3507, 10.3506) -> (-26.3408, 8.3327)
  line L28 (-27.8127, 5.4623) -> (-29.6231, 7.7754)
  line L29 (-28.5203, 8.6384) -> (-26.71, 6.3254)
  line L30 (-26.8298, 5.3425) -> (-29.5032, 8.7583)
  line L31 (-27.5492, 1.506) -> (-26.5216, 0.4784)
  line L32 (-27.4784, -0.4784) -> (-28.506, 0.5492)
  line L33 (-28.506, 1.506) -> (-26.5216, -0.4784)
  line L34 (-28.5099, 2.5667) -> (-29.1142, 3.171)
  line L35 (-27.8638, 4.4215) -> (-27.2594, 3.8171)
  line L36 (-27.8847, 3.1919) -> (-28.489, 3.7963)
  line L37 (-41.95, 9.7703) -> (-82.1997, 9.7703)
  line L38 (-40.45, 1.0303) -> (-40.45, 8.2703)
  line L39 (-82.1997, -0.4697) -> (-41.95, -0.4697)
  line L40 (-83.6997, 8.2703) -> (-83.6997, 1.0303)
  arc A1 centre (-35, 12) radius 1.1493 clockwise from (-35.8952, 12.7207) to (-34.1048, 11.2793)
  arc A2 centre (-37.1289, 9.3556) radius 1.1493 clockwise from (-36.2337, 8.6349) to (-38.0242, 10.0763)
  arc A3 centre (-36.2581, 3.674) radius 0.9735 clockwise from (-37.0681, 4.214) to (-35.4481, 3.134)
  arc A4 centre (-38.2581, 0.674) radius 0.9735 clockwise from (-37.4481, 0.134) to (-39.0681, 1.214)
  arc A5 centre (-30.1982, 12.1802) radius 1.3416 clockwise from (-31.2459, 13.0183) to (-29.1506, 11.3422)
  arc A6 centre (-33.1221, 8.5251) radius 1.3416 clockwise from (-32.0744, 7.687) to (-34.1698, 9.3632)
  arc A7 centre (-30.3889, 6.3932) radius 0.7124 clockwise from (-31.0413, 6.6794) to (-29.7365, 6.1071)
  arc A8 centre (-31, 5) radius 0.7124 clockwise from (-30.3476, 4.7139) to (-31.6524, 5.2861)
  arc A9 centre (-35.6538, 6.8295) radius 0.5678 clockwise from (-36.0645, 6.4375) to (-35.2431, 7.2215)
  arc A10 centre (-33.0792, 4.1323) radius 0.5678 clockwise from (-32.6686, 4.5243) to (-33.4899, 3.7403)
  arc A11 centre (-30.4319, 2.1186) radius 0.9 clockwise from (-31.0932, 2.7291) to (-29.7705, 1.5082)
  arc A12 centre (-32.5505, -0.1766) radius 0.9 clockwise from (-31.8892, -0.787) to (-33.2118, 0.4339)
  arc A13 centre (-27.3507, 10.3506) radius 0.6595 clockwise from (-27.9405, 10.0554) to (-26.7609, 10.6458)
  arc A14 centre (-26.3408, 8.3327) radius 0.6595 clockwise from (-25.751, 8.6279) to (-26.9306, 8.0376)
  arc A15 centre (-27.2614, 5.8938) radius 0.7002 clockwise from (-26.71, 6.3254) to (-27.8127, 5.4623)
  arc A16 centre (-29.0717, 8.2069) radius 0.7002 clockwise from (-29.6231, 7.7754) to (-28.5203, 8.6384)
  arc A17 centre (-28.0276, 1.0276) radius 0.6765 clockwise from (-28.506, 0.5492) to (-27.5492, 1.506)
  arc A18 centre (-27, 0) radius 0.6765 clockwise from (-26.5216, 0.4784) to (-27.4784, -0.4784)
  circle C1 centre (-34.4206, 1.5996) radius 0.9525
  circle C2 centre (-38.4131, 6.7874) radius 0.6048
  circle C3 centre (-38.2296, 12.5475) radius 0.5937
  arc A19 centre (-27.8847, 3.1919) radius 0.8842 clockwise from (-27.2594, 3.8171) to (-28.5099, 2.5667)
  arc A20 centre (-28.489, 3.7963) radius 0.8842 clockwise from (-29.1142, 3.171) to (-27.8638, 4.4215)
  arc A21 centre (-41.95, 8.2703) radius 1.5 clockwise from (-41.95, 9.7703) to (-40.45, 8.2703)
  arc A22 centre (-41.95, 1.0303) radius 1.5 clockwise from (-40.45, 1.0303) to (-41.95, -0.4697)
  arc A23 centre (-82.1997, 1.0303) radius 1.5 clockwise from (-82.1997, -0.4697) to (-83.6997, 1.0303)
  arc A24 centre (-82.1997, 8.2703) radius 1.5 clockwise from (-83.6997, 8.2703) to (-82.1997, 9.7703)
  point P59 (-29.5032, 8.7583)
  point P60 (-26.8298, 5.3425)
  point P67 (-26.5216, -0.4784)
  point P68 (-28.506, 1.506)
  horizontal L5
  vertical L6
  tangent L7 A1
  tangent A1 L8
  parallel L7 L8
  tangent L8 A2
  tangent L7 A2
  tangent L10 A3
  tangent A3 L11
  parallel L10 L11
  tangent L11 A4
  tangent L10 A4
  tangent L13 A5
  tangent A5 L14
  parallel L13 L14
  tangent L14 A6
  tangent L13 A6
  tangent L16 A7
  tangent A7 L17
  parallel L16 L17
  tangent L17 A8
  tangent L16 A8
  tangent L19 A9
  tangent A9 L20
  parallel L19 L20
  tangent L20 A10
  tangent L19 A10
  tangent L22 A11
  tangent A11 L23
  parallel L22 L23
  tangent L23 A12
  tangent L22 A12
  tangent L25 A13
  tangent A13 L26
  parallel L25 L26
  tangent L26 A14
  tangent L25 A14
  tangent L28 A15
  tangent A15 L29
  parallel L28 L29
  tangent L29 A16
  tangent L28 A16
  midpoint A16 P59
  midpoint A15 P60
  tangent L31 A17
  tangent A17 L32
  parallel L31 L32
  tangent L32 A18
  tangent L31 A18
  midpoint A18 P67
  midpoint A17 P68
  tangent L34 A19
  tangent A19 L35
  parallel L34 L35
  tangent L35 A20
  tangent L34 A20
sketch "Sketch38" plane through (0, 59.802, 0) normal (0, 1, 0) x axis (-1, 0, 0)
  line L1 (-84.2, -2.019) -> (-84.2, 21.6)
  line L2 (-4.6, -2.019) -> (-84.2, -2.019)
  line L3 (-4.6, 21.6) -> (-4.6, -2.019)
  line L4 (-84.2, 21.6) -> (-4.6, 21.6)
  line L5 (-77.3528, 12.5427) -> (-78.4865, 10.9382)
  line L6 (-79.781, 11.8529) -> (-78.6472, 13.4573)
  line L7 (-78, 13) -> (-79.1337, 11.3955)
  line L8 (-74.994, 11.3053) -> (-74.994, 12.435)
  line L9 (-73.1108, 12.435) -> (-73.1108, 11.3053)
  line L10 (-74.0524, 11.3053) -> (-74.0524, 12.435)
  line L11 (-66.3726, 12.3308) -> (-67.9856, 10.8185)
  line L12 (-69.2404, 12.157) -> (-67.6274, 13.6692)
  line L13 (-67, 13) -> (-68.613, 11.4878)
  line L14 (-62.7492, 11.0575) -> (-63.4917, 12.4162)
  line L15 (-61.7483, 13.369) -> (-61.0058, 12.0103)
  line L16 (-61.8775, 11.5339) -> (-62.62, 12.8926)
  line L17 (-54.0253, 13.6651) -> (-54.9479, 11.4991)
  line L18 (-56.6277, 12.2146) -> (-55.705, 14.3806)
  line L19 (-54.8651, 14.0229) -> (-55.7878, 11.8569)
  line L20 (-58.9598, 10.8731) -> (-59.5596, 11.8522)
  line L21 (-58.2177, 12.6741) -> (-57.618, 11.6951)
  line L22 (-58.2889, 11.2841) -> (-58.8886, 12.2632)
  line L23 (-48.1114, 13.411) -> (-50.0029, 10.7581)
  line L24 (-51.331, 11.705) -> (-49.4395, 14.3579)
  line L25 (-48.7755, 13.8845) -> (-50.6669, 11.2316)
  line L26 (-45.6175, 14.8966) -> (-44.2748, 11.4386)
  line L27 (-45.3411, 11.0246) -> (-46.6838, 14.4826)
  line L28 (-46.1506, 14.6896) -> (-44.8079, 11.2316)
  line L29 (-41.3935, 14.4725) -> (-40.3798, 12.0987)
  line L30 (-42.5928, 11.1537) -> (-43.6065, 13.5275)
  line L31 (-42.5, 14) -> (-41.4863, 11.6262)
  line L32 (-53.21, 11.0022) -> (-53.7686, 11.914)
  line L33 (-53.1014, 12.3227) -> (-52.5428, 11.4109)
  line L34 (-52.8764, 11.2065) -> (-53.435, 12.1184)
  line L35 (-47.4324, 10.631) -> (-48.0964, 11.1045)
  line L36 (-47.2401, 12.3056) -> (-46.576, 11.8321)
  line L37 (-47.0042, 11.2316) -> (-47.6682, 11.705)
  line L38 (-71.3889, 10.8763) -> (-72.0348, 11.7293)
  line L39 (-71.0964, 12.4398) -> (-70.4506, 11.5868)
  line L40 (-70.9197, 11.2316) -> (-71.5656, 12.0846)
  line L41 (-82.2168, 10.9584) -> (-82.9257, 11.7145)
  line L42 (-81.7962, 12.7733) -> (-81.0874, 12.0172)
  line L43 (-81.6521, 11.4878) -> (-82.3609, 12.2439)
  line L44 (-41.95, 9.7703) -> (-82.1997, 9.7703)
  line L45 (-40.45, 1.0303) -> (-40.45, 8.2703)
  line L46 (-82.1997, -0.4697) -> (-41.95, -0.4697)
  line L47 (-83.6997, 8.2703) -> (-83.6997, 1.0303)
  arc A1 centre (-78, 13) radius 0.7925 clockwise from (-78.6472, 13.4573) to (-77.3528, 12.5427)
  arc A2 centre (-79.1337, 11.3955) radius 0.7925 clockwise from (-78.4865, 10.9382) to (-79.781, 11.8529)
  arc A3 centre (-74.0524, 11.3053) radius 0.9416 clockwise from (-73.1108, 11.3053) to (-74.994, 11.3053)
  arc A4 centre (-74.0524, 12.435) radius 0.9416 clockwise from (-74.994, 12.435) to (-73.1108, 12.435)
  arc A5 centre (-67, 13) radius 0.9173 clockwise from (-67.6274, 13.6692) to (-66.3726, 12.3308)
  arc A6 centre (-68.613, 11.4878) radius 0.9173 clockwise from (-67.9856, 10.8185) to (-69.2404, 12.157)
  arc A7 centre (-61.8775, 11.5339) radius 0.9934 clockwise from (-61.0058, 12.0103) to (-62.7492, 11.0575)
  arc A8 centre (-62.62, 12.8926) radius 0.9934 clockwise from (-63.4917, 12.4162) to (-61.7483, 13.369)
  arc A9 centre (-54.8651, 14.0229) radius 0.9129 clockwise from (-55.705, 14.3806) to (-54.0253, 13.6651)
  arc A10 centre (-55.7878, 11.8569) radius 0.9129 clockwise from (-54.9479, 11.4991) to (-56.6277, 12.2146)
  arc A11 centre (-58.2889, 11.2841) radius 0.7868 clockwise from (-57.618, 11.6951) to (-58.9598, 10.8731)
  arc A12 centre (-58.8886, 12.2632) radius 0.7868 clockwise from (-59.5596, 11.8522) to (-58.2177, 12.6741)
  arc A13 centre (-48.7755, 13.8845) radius 0.8155 clockwise from (-49.4395, 14.3579) to (-48.1114, 13.411)
  arc A14 centre (-50.6669, 11.2316) radius 0.8155 clockwise from (-50.0029, 10.7581) to (-51.331, 11.705)
  arc A15 centre (-46.1506, 14.6896) radius 0.5719 clockwise from (-46.6838, 14.4826) to (-45.6175, 14.8966)
  arc A16 centre (-44.8079, 11.2316) radius 0.5719 clockwise from (-44.2748, 11.4386) to (-45.3411, 11.0246)
  arc A17 centre (-42.5, 14) radius 1.2032 clockwise from (-43.6065, 13.5275) to (-41.3935, 14.4725)
  arc A18 centre (-41.4863, 11.6262) radius 1.2032 clockwise from (-40.3798, 12.0987) to (-42.5928, 11.1537)
  arc A19 centre (-52.8764, 11.2065) radius 0.3912 clockwise from (-52.5428, 11.4109) to (-53.21, 11.0022)
  arc A20 centre (-53.435, 12.1184) radius 0.3912 clockwise from (-53.7686, 11.914) to (-53.1014, 12.3227)
  arc A21 centre (-47.0042, 11.2316) radius 0.7376 clockwise from (-46.576, 11.8321) to (-47.4324, 10.631)
  arc A22 centre (-47.6682, 11.705) radius 0.7376 clockwise from (-48.0964, 11.1045) to (-47.2401, 12.3056)
  arc A23 centre (-70.9197, 11.2316) radius 0.5885 clockwise from (-70.4506, 11.5868) to (-71.3889, 10.8763)
  arc A24 centre (-71.5656, 12.0846) radius 0.5885 clockwise from (-72.0348, 11.7293) to (-71.0964, 12.4398)
  arc A25 centre (-81.6521, 11.4878) radius 0.7741 clockwise from (-81.0874, 12.0172) to (-82.2168, 10.9584)
  arc A26 centre (-82.3609, 12.2439) radius 0.7741 clockwise from (-82.9257, 11.7145) to (-81.7962, 12.7733)
  circle C1 centre (-64.9685, 11.4417) radius 1
  circle C2 centre (-76.5, 11.5) radius 0.6505
  arc A27 centre (-41.95, 8.2703) radius 1.5 clockwise from (-41.95, 9.7703) to (-40.45, 8.2703)
  arc A28 centre (-41.95, 1.0303) radius 1.5 clockwise from (-40.45, 1.0303) to (-41.95, -0.4697)
  arc A29 centre (-82.1997, 1.0303) radius 1.5 clockwise from (-82.1997, -0.4697) to (-83.6997, 1.0303)
  arc A30 centre (-82.1997, 8.2703) radius 1.5 clockwise from (-83.6997, 8.2703) to (-82.1997, 9.7703)
  tangent L5 A1
  tangent A1 L6
  parallel L5 L6
  tangent L6 A2
  tangent L5 A2
  tangent L8 A3
  tangent A3 L9
  parallel L8 L9
  tangent L9 A4
  tangent L8 A4
  tangent L11 A5
  tangent A5 L12
  parallel L11 L12
  tangent L12 A6
  tangent L11 A6
  tangent L14 A7
  tangent A7 L15
  parallel L14 L15
  tangent L15 A8
  tangent L14 A8
  tangent L17 A9
  tangent A9 L18
  parallel L17 L18
  tangent L18 A10
  tangent L17 A10
  tangent L20 A11
  tangent A11 L21
  parallel L20 L21
  tangent L21 A12
  tangent L20 A12
  tangent L23 A13
  tangent A13 L24
  parallel L23 L24
  tangent L24 A14
  tangent L23 A14
  tangent L26 A15
  tangent A15 L27
  parallel L26 L27
  tangent L27 A16
  tangent L26 A16
  tangent L29 A17
  tangent A17 L30
  parallel L29 L30
  tangent L30 A18
  tangent L29 A18
  tangent L32 A19
  tangent A19 L33
  parallel L32 L33
  tangent L33 A20
  tangent L32 A20
  parallel L21 L34
  tangent L35 A21
  tangent A21 L36
  parallel L35 L36
  tangent L36 A22
  tangent L35 A22
  perpendicular L23 L37
  tangent L38 A23
  tangent A23 L39
  parallel L38 L39
  tangent L39 A24
  tangent L38 A24
  tangent L41 A25
  tangent A25 L42
  parallel L41 L42
  tangent L42 A26
  tangent L41 A26
  perpendicular L13 L43
extrude "Extrude50" add sketch "Sketch35" profile of C2 L16 against normal blind 2.8
extrude "Extrude51" cut sketch "Sketch35" profile of C2 against normal blind 2.8 and against normal blind 1.2
sketch "Sketch39" plane through (87.9, 0, 0) normal (-1, 0, 0) x axis (0, -1, 0)
  line L1 (-37.5941, 5.5134) -> (-42.6941, 5.5134)
  line L2 (-42.6941, 1.4134) -> (-37.5941, 1.4134)
  line L3 (-36.6258, -0.6871) -> (-36.1258, 0.3129)
  line L4 (-36.8742, 0.6871) -> (-37.3742, -0.3129)
  line L5 (-42.0276, 9.5417) -> (-40.8255, 7.1376)
  line L6 (-38.6336, 8.2336) -> (-39.8356, 10.6377)
  line L7 (-44.3847, -0.2206) -> (-43.6433, -1.2821)
  line L8 (-42.503, -0.4857) -> (-43.2444, 0.5758)
  line L9 (-39.809, -1.2436) -> (-38.3992, -0.0011)
  line L10 (-39.1812, 0.8862) -> (-40.591, -0.3564)
  line L11 (-32.6474, 3.0718) -> (-31.5271, 3.9384)
  line L12 (-32.7999, 5.5837) -> (-33.9202, 4.7171)
  line L13 (-47.0891, -0.5864) -> (-45.9587, 2.459)
  line L14 (-47.497, 3.03) -> (-48.6275, -0.0154)
  curve K1 (-49.7958, -1.519) -> (-53.502, -1.4707)
  line L15 (-34.6, -1.519) -> (-42.7898, -1.519)
  line L16 (-34.6, 0.4) -> (-34.6, -1.519)
  line L17 (-20.9875, 1.4) -> (-33.6, 1.4)
  line L18 (-19.9875, -1.519) -> (-19.9875, 0.4)
  line L19 (-6.2042, -1.519) -> (-19.9875, -1.519)
  curve K2 (-2.4862, -1.4711) -> (-6.2042, -1.519)
  line L20 (-2.4862, 23.1) -> (-2.4862, -1.4711)
  line L21 (-14.0576, 23.1) -> (-2.4862, 23.1)
  line L22 (-39.9941, 21.6) -> (-15.9941, 21.6)
  line L23 (-53.502, 23.1) -> (-41.9306, 23.1)
  line L24 (-53.502, -1.4707) -> (-53.502, 23.1)
  line L25 (-43.3565, -1.519) -> (-49.7958, -1.519)
  arc A1 centre (-37.5941, 3.4634) radius 2.05 clockwise from (-37.5941, 5.5134) to (-37.5941, 1.4134)
  arc A2 centre (-42.6941, 3.4634) radius 2.05 clockwise from (-42.6941, 1.4134) to (-42.6941, 5.5134)
  arc A3 centre (-37, -0.5) radius 0.4184 clockwise from (-36.6258, -0.6871) to (-37.3742, -0.3129)
  arc A4 centre (-36.5, 0.5) radius 0.4184 clockwise from (-36.8742, 0.6871) to (-36.1258, 0.3129)
  arc A5 centre (-40.9316, 10.0897) radius 1.2254 clockwise from (-42.0276, 9.5417) to (-39.8356, 10.6377)
  arc A6 centre (-39.7296, 7.6856) radius 1.2254 clockwise from (-38.6336, 8.2336) to (-40.8255, 7.1376)
  arc A7 centre (-43.8145, 0.1776) radius 0.6955 clockwise from (-44.3847, -0.2206) to (-43.2444, 0.5758)
  arc A8 centre (-43.0731, -0.8839) radius 0.6955 clockwise from (-42.503, -0.4857) to (-42.7898, -1.519)
  arc A9 centre (-40.2, -0.8) radius 0.5914 clockwise from (-39.809, -1.2436) to (-40.591, -0.3564)
  arc A10 centre (-38.7902, 0.4426) radius 0.5914 clockwise from (-39.1812, 0.8862) to (-38.3992, -0.0011)
  arc A11 centre (-33.2838, 3.8945) radius 1.0401 clockwise from (-32.6474, 3.0718) to (-33.9202, 4.7171)
  arc A12 centre (-32.1635, 4.7611) radius 1.0401 clockwise from (-32.7999, 5.5837) to (-31.5271, 3.9384)
  arc A13 centre (-47.8583, -0.3009) radius 0.8205 clockwise from (-47.0891, -0.5864) to (-48.6275, -0.0154)
  arc A14 centre (-46.7279, 2.7445) radius 0.8205 clockwise from (-47.497, 3.03) to (-45.9587, 2.459)
  arc A15 centre (-33.6, 0.4) radius 1 clockwise from (-34.6, 0.4) to (-33.6, 1.4)
  arc A16 centre (-20.9875, 0.4) radius 1 clockwise from (-20.9875, 1.4) to (-19.9875, 0.4)
  arc A17 centre (-14.0576, 22.6) radius 0.5 clockwise from (-14.5418, 22.725) to (-14.0576, 23.1)
  arc A18 centre (-15.9941, 23.1) radius 1.5 clockwise from (-14.5418, 22.725) to (-15.9941, 21.6)
  arc A19 centre (-39.9941, 23.1) radius 1.5 clockwise from (-39.9941, 21.6) to (-41.4465, 22.725)
  arc A20 centre (-41.9306, 22.6) radius 0.5 clockwise from (-41.9306, 23.1) to (-41.4465, 22.725)
  circle C1 centre (-37.5941, 3.4634) radius 2.5
  arc A21 centre (-43.0731, -0.8839) radius 0.6955 clockwise from (-43.3565, -1.519) to (-43.6433, -1.2821)
  concentric A1 C1
  dimension "d341" diameter C1 = 5
sketch "Sketch41" plane through (90.7, 0, 0) normal (1, 0, 0) x axis (0, 1, 0)
  line L1 (42.6941, 5.5134) -> (37.5941, 5.5134)
  line L2 (37.5941, 1.4134) -> (42.6941, 1.4134)
  line L3 (36.1258, 0.3129) -> (36.6258, -0.6871)
  line L4 (37.3742, -0.3129) -> (36.8742, 0.6871)
  line L5 (40.8255, 7.1376) -> (42.0276, 9.5417)
  line L6 (39.8356, 10.6377) -> (38.6336, 8.2336)
  line L7 (43.6433, -1.2821) -> (44.3847, -0.2206)
  line L8 (43.2444, 0.5758) -> (42.503, -0.4857)
  line L9 (38.3992, -0.0011) -> (39.809, -1.2436)
  line L10 (40.591, -0.3564) -> (39.1812, 0.8862)
  line L11 (31.5271, 3.9384) -> (32.6474, 3.0718)
  line L12 (33.9202, 4.7171) -> (32.7999, 5.5837)
  line L13 (45.9587, 2.459) -> (47.0891, -0.5864)
  line L14 (48.6275, -0.0154) -> (47.497, 3.03)
  line L15 (33.6, 2.4) -> (20.9875, 2.4)
  line L16 (35.6, -2.019) -> (35.6, 0.4)
  line L17 (53.302, -2.019) -> (35.6, -2.019)
  line L18 (53.302, 21.6) -> (53.302, -2.019)
  line L19 (2.6862, 21.6) -> (53.302, 21.6)
  line L20 (2.6862, -2.019) -> (2.6862, 21.6)
  line L21 (18.9875, -2.019) -> (2.6862, -2.019)
  line L22 (18.9875, 0.4) -> (18.9875, -2.019)
  line L23 (42.6941, 1.4134) -> (42.6941, 5.5134)
  line L24 (41.9463, 1.4134) -> (41.9463, 5.5134)
  line L25 (43.8675, 1.7824) -> (43.1406, 5.4642)
  arc A1 centre (37.5941, 3.4634) radius 2.05 clockwise from (37.5941, 1.4134) to (37.5941, 5.5134)
  arc A2 centre (36.5, 0.5) radius 0.4184 clockwise from (36.1258, 0.3129) to (36.8742, 0.6871)
  arc A3 centre (37, -0.5) radius 0.4184 clockwise from (37.3742, -0.3129) to (36.6258, -0.6871)
  arc A4 centre (39.7296, 7.6856) radius 1.2254 clockwise from (40.8255, 7.1376) to (38.6336, 8.2336)
  arc A5 centre (40.9316, 10.0897) radius 1.2254 clockwise from (39.8356, 10.6377) to (42.0276, 9.5417)
  arc A6 centre (43.0731, -0.8839) radius 0.6955 clockwise from (43.6433, -1.2821) to (42.503, -0.4857)
  arc A7 centre (43.8145, 0.1776) radius 0.6955 clockwise from (43.2444, 0.5758) to (44.3847, -0.2206)
  arc A8 centre (38.7902, 0.4426) radius 0.5914 clockwise from (38.3992, -0.0011) to (39.1812, 0.8862)
  arc A9 centre (40.2, -0.8) radius 0.5914 clockwise from (40.591, -0.3564) to (39.809, -1.2436)
  arc A10 centre (32.1635, 4.7611) radius 1.0401 clockwise from (31.5271, 3.9384) to (32.7999, 5.5837)
  arc A11 centre (33.2838, 3.8945) radius 1.0401 clockwise from (33.9202, 4.7171) to (32.6474, 3.0718)
  arc A12 centre (46.7279, 2.7445) radius 0.8205 clockwise from (45.9587, 2.459) to (47.497, 3.03)
  arc A13 centre (47.8583, -0.3009) radius 0.8205 clockwise from (48.6275, -0.0154) to (47.0891, -0.5864)
  arc A14 centre (33.6, 0.4) radius 2 clockwise from (33.6, 2.4) to (35.6, 0.4)
  arc A15 centre (20.9875, 0.4) radius 2 clockwise from (18.9875, 0.4) to (20.9875, 2.4)
  circle C1 centre (41.9463, 3.4634) radius 2.05
  arc A16 centre (42.6941, 3.4634) radius 2.05 clockwise from (42.6941, 5.5134) to (43.1406, 5.4642)
  arc A17 centre (42.6941, 3.4634) radius 2.05 clockwise from (43.8675, 1.7824) to (42.6941, 1.4134)
  point P3 (42.6941, 5.5134)
  point P58 (42.6941, 5.5134)
  point P4 (42.6941, 1.4134)
  point P59 (42.6941, 1.4134)
  point P60 (41.9463, 5.5134)
  point P61 (41.9463, 1.4134)
  point P62 (41.9463, 3.4634)
  coincident P3 P58
  coincident P4 P59
  coincident L1 P60
  coincident L2 P61
  perpendicular L2 L24
  midpoint L24 P62
  coincident P61 C1
extrude "Extrude52" cut sketch "Sketch39" profile of L1 A1 L2 C1 against normal blind 1.5
sketch "Sketch40" plane through (90.7, 0, 0) normal (1, 0, 0) x axis (0, 1, 0)
  line L1 (36.1258, 0.3129) -> (36.6258, -0.6871)
  line L2 (37.3742, -0.3129) -> (36.8742, 0.6871)
  line L3 (40.8255, 7.1376) -> (42.0276, 9.5417)
  line L4 (39.8356, 10.6377) -> (38.6336, 8.2336)
  line L5 (43.6433, -1.2821) -> (44.3847, -0.2206)
  line L6 (43.2444, 0.5758) -> (42.503, -0.4857)
  line L7 (38.3992, -0.0011) -> (39.809, -1.2436)
  line L8 (40.591, -0.3564) -> (39.1812, 0.8862)
  line L9 (31.5271, 3.9384) -> (32.6474, 3.0718)
  line L10 (33.9202, 4.7171) -> (32.7999, 5.5837)
  line L11 (45.9587, 2.459) -> (47.0891, -0.5864)
  line L12 (48.6275, -0.0154) -> (47.497, 3.03)
  line L13 (37.5941, 1.4134) -> (42.6941, 1.4134)
  line L14 (42.6941, 5.5134) -> (37.5941, 5.5134)
  line L15 (33.6, 2.4) -> (20.9875, 2.4)
  line L16 (35.6, -2.019) -> (35.6, 0.4)
  line L17 (53.302, -2.019) -> (35.6, -2.019)
  line L18 (53.302, 21.6) -> (53.302, -2.019)
  line L19 (2.6862, 21.6) -> (53.302, 21.6)
  line L20 (2.6862, -2.019) -> (2.6862, 21.6)
  line L21 (18.9875, -2.019) -> (2.6862, -2.019)
  line L22 (18.9875, 0.4) -> (18.9875, -2.019)
  line L23 (45.372, 6.2481) -> (34.9148, 6.2481)
  line L24 (45.372, 0.9103) -> (45.372, 6.2481)
  line L25 (34.9148, 0.9103) -> (45.372, 0.9103)
  line L26 (34.9148, 6.2481) -> (34.9148, 0.9103)
  line L27 (43.8675, 1.7824) -> (43.1406, 5.4642)
  arc A1 centre (36.5, 0.5) radius 0.4184 clockwise from (36.1258, 0.3129) to (36.8742, 0.6871)
  arc A2 centre (37, -0.5) radius 0.4184 clockwise from (37.3742, -0.3129) to (36.6258, -0.6871)
  arc A3 centre (39.7296, 7.6856) radius 1.2254 clockwise from (40.8255, 7.1376) to (38.6336, 8.2336)
  arc A4 centre (40.9316, 10.0897) radius 1.2254 clockwise from (39.8356, 10.6377) to (42.0276, 9.5417)
  arc A5 centre (43.0731, -0.8839) radius 0.6955 clockwise from (43.6433, -1.2821) to (42.503, -0.4857)
  arc A6 centre (43.8145, 0.1776) radius 0.6955 clockwise from (43.2444, 0.5758) to (44.3847, -0.2206)
  arc A7 centre (38.7902, 0.4426) radius 0.5914 clockwise from (38.3992, -0.0011) to (39.1812, 0.8862)
  arc A8 centre (40.2, -0.8) radius 0.5914 clockwise from (40.591, -0.3564) to (39.809, -1.2436)
  arc A9 centre (32.1635, 4.7611) radius 1.0401 clockwise from (31.5271, 3.9384) to (32.7999, 5.5837)
  arc A10 centre (33.2838, 3.8945) radius 1.0401 clockwise from (33.9202, 4.7171) to (32.6474, 3.0718)
  arc A11 centre (46.7279, 2.7445) radius 0.8205 clockwise from (45.9587, 2.459) to (47.497, 3.03)
  arc A12 centre (47.8583, -0.3009) radius 0.8205 clockwise from (48.6275, -0.0154) to (47.0891, -0.5864)
  arc A13 centre (37.5941, 3.4634) radius 2.05 clockwise from (37.5941, 1.4134) to (37.5941, 5.5134)
  arc A14 centre (33.6, 0.4) radius 2 clockwise from (33.6, 2.4) to (35.6, 0.4)
  arc A15 centre (20.9875, 0.4) radius 2 clockwise from (18.9875, 0.4) to (20.9875, 2.4)
  arc A16 centre (42.6941, 3.4634) radius 2.05 clockwise from (42.6941, 5.5134) to (43.1406, 5.4642)
  arc A17 centre (42.6941, 3.4634) radius 2.05 clockwise from (43.8675, 1.7824) to (42.6941, 1.4134)
  horizontal L23
  vertical L24
  horizontal L25
  vertical L26
extrude "Extrude54" add sketch "Sketch41" profile of L1 L2 C1 against normal blind 1.2
extrude "Extrude55" cut sketch "Sketch41" profile of C1 against normal blind 1.2
extrude "Extrude53" new body sketch "Sketch40" profile of A1 A6 A7 L13 A13 L14 A14 L23 L24 L25 L26 against normal blind 2.8
combine "Combine6"
remove_body "RemoveBody1"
